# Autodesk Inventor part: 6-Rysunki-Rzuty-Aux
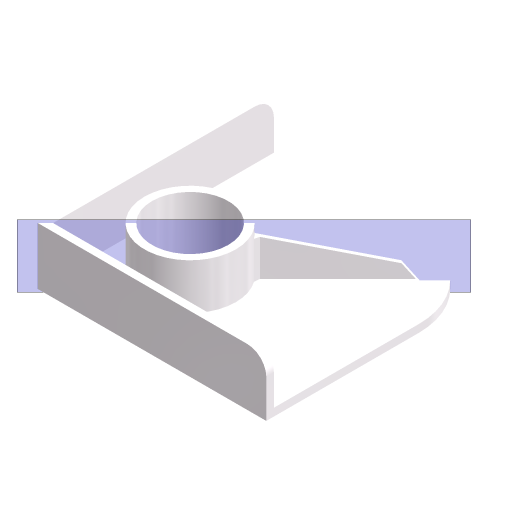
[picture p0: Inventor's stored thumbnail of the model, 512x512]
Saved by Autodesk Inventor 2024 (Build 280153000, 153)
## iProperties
Company: ATC
Shininess: 21.0
Length Units: 11269
Angle Units: 11279
Time Units: 11290
Mass Units: 11283
Length Display Precision: 3
Angle Display Precision: 2
Compacted: True
Created: 2023-03
Part Number: 6-Rysunki-Rzuty-Aux
Document SubType Name: Modeling
Designer: Andrzej Jaskulski
Material: Kurs-AJ
Density: 1 g/cm^3
Appearance: Kurs-AJ
Checked By: A.J.
Engr Approved By: Andrzej Jaskulski
Mfg Approved By: Andrzej Jaskulski
Authority: A.J.
Density: 0.0
Volumn: 0.0
Area: 0.0
PropertySet Name: Model Information
Control State: 0
Master: False
Checked Out: False
Title: A.J.: Kurs R2024-MEP
Author: Andrzej Jaskulski
Revision Number: 1/24
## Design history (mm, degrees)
sketch "Sketch1"
  geometry: L1 (0, 0)-(60, 0); L2 (60, 0)-(60, 60); L3 (60, 60)-(0, 60); L4 (0, 60)-(0, 0)
  constraints: 8 end point, 2 parallel, 1 horizontal, 1 perpendicular, 1 other
  dimensions: "d0" = 60 distance of L1.start L1.end (= x); "d1" = 60 distance of L1.end L2.end (= y)
extrude "Baza" new body sketch "Sketch1" distance "d2" = 15 (= h); taper "d3" = 0 deg
sketch "Sketch3"
  geometry: L1 (0, 0)-(0, 60) reference; L2 (60, 0)-(0, 0) reference; 1 further point
  dimensions: "d9" = 20 distance from line of L1 point (20, 20) (= Lx); "d10" = 20 distance from line of L2 point (20, 20) (= Ly)
hole "Otwór" sketch "Sketch3" diameter "d7" = 20 (= d); stored, may be unused: countersink angle "d18" = 60 deg, drill point angle "d20" = 118 deg; dims "d8" = 6, "d16" = 4, "d17" = 2, "d19" = 8
fillet "Zaokrąglenie1" dims "d4" = 20 (= d)
fillet "Zaokrąglenie2" dims "d5" = 5 (= 0.5 x r)
feature "Skorupa1" dims "d6" = 2
workplane "Work Plane3"
feature "Rib2" dims "d25" = 1, "d26" = 2
chamfer "Chamfer1" distance "d27" = 1; stored, may be unused: second distance "d28" = 1, angle "d29" = 45 deg
node "Bryła1"
node "Korpusy bryłowe"
node "Korpusy powierzchniowe"
sketch "Sketch4"
  geometry: L1 (-42.108, -2.65)-(-67.526, -8.433); L2 (-67.526, -8.433)-(-69.338, -10.872); L3 (0, -15)-(0, 0) reference
  constraints: 4 end point
other parameters: "inna_glob" = 19 [user parameter], "inna2_glob" = 21 [user parameter], "x" = 60 [user parameter; used in 1 equation term], "y" = 60 [user parameter; used in 1 equation term], "h" = 15 [user parameter; used in 1 equation term], "Lx" = 20 [user parameter; used in 1 equation term], "Ly" = 20 [user parameter; used in 1 equation term], "L2" = 1 [user parameter], "d" = 20 (= 2 x r) [user parameter; used in 2 equation terms], "wys_glob" = 15 [user parameter]
